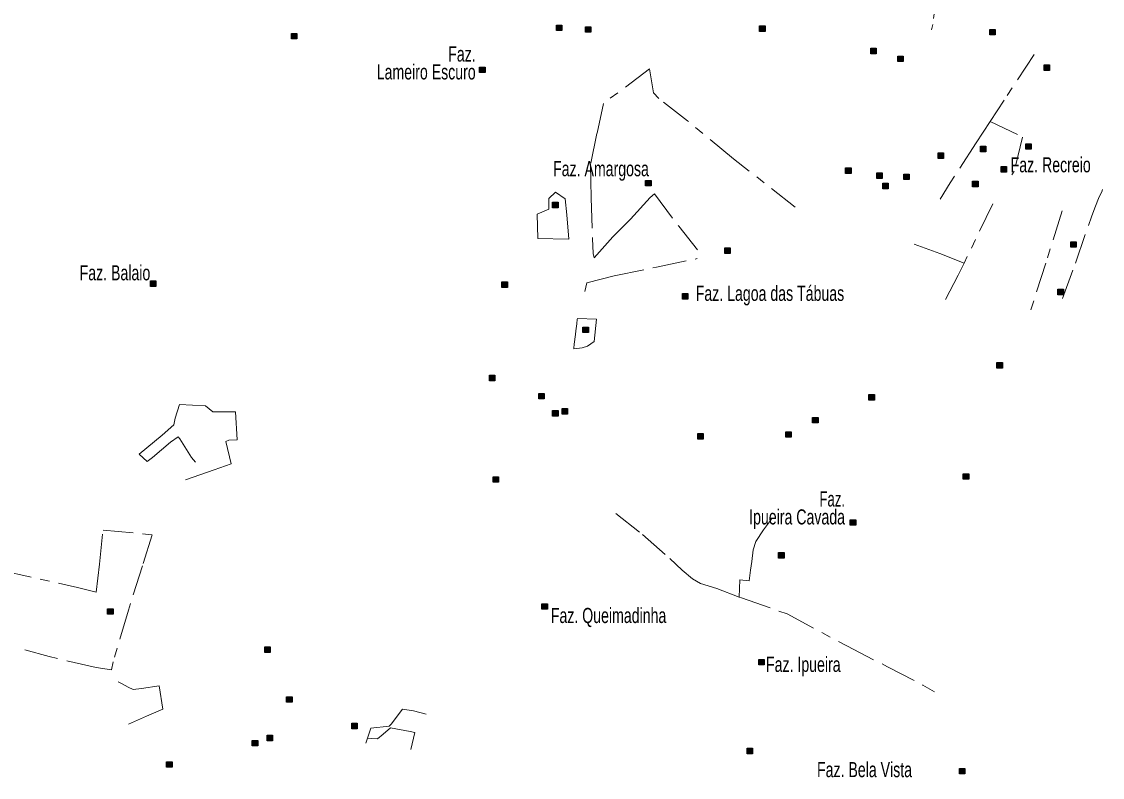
# Model space of a CAD drawing. Extents: x 445.4 to 500, y 8728.7 to 8784.
# Drawn here: x 488.54 to 500, y 8738.13 to 8746.14 of the extents above; entities that cross this region are included whole.
import ezdxf
from ezdxf.enums import TextEntityAlignment as Align

# ---------------------------------------------------------------- set-up
doc = ezdxf.new("R2010")
doc.units = 0
doc.header["$LTSCALE"] = 0.064
doc.linetypes.add('DOT_DASHED', pattern=[7.7, 5, -1.2, 0.3, -1.2])
doc.layers.add('2', color=7, linetype='Continuous', lineweight=25)
doc.layers.add('22', color=7, linetype='DOT_DASHED', lineweight=13)
doc.layers.add('61', color=7, linetype='Continuous')

msp = doc.modelspace()

# ---------------------------------------------------------------- hatches: boundary and pattern name
at = {"layer": '2'}
for points in [[(494.2125, 8746.1016), (494.2705, 8746.1016), (494.2705, 8746.0436), (494.2125, 8746.0436)], [(494.5213, 8746.0849), (494.5793, 8746.0849), (494.5793, 8746.0269), (494.5213, 8746.0269)], [(496.3667, 8746.0936), (496.4247, 8746.0936), (496.4247, 8746.0356), (496.3667, 8746.0356)], [(498.8058, 8746.056), (498.8638, 8746.056), (498.8638, 8745.998), (498.8058, 8745.998)], [(491.4052, 8746.0138), (491.4632, 8746.0138), (491.4632, 8745.9558), (491.4052, 8745.9558)], [(497.5448, 8745.8569), (497.6028, 8745.8569), (497.6028, 8745.7989), (497.5448, 8745.7989)], [(497.8307, 8745.773), (497.8887, 8745.773), (497.8887, 8745.715), (497.8307, 8745.715)], [(493.3992, 8745.6577), (493.4572, 8745.6577), (493.4572, 8745.5997), (493.3992, 8745.5997)], [(499.3821, 8745.68), (499.4401, 8745.68), (499.4401, 8745.622), (499.3821, 8745.622)], [(498.7073, 8744.8186), (498.7653, 8744.8186), (498.7653, 8744.7606), (498.7073, 8744.7606)], [(499.1888, 8744.8442), (499.2468, 8744.8442), (499.2468, 8744.7862), (499.1888, 8744.7862)], [(498.2595, 8744.7472), (498.3175, 8744.7472), (498.3175, 8744.6892), (498.2595, 8744.6892)], [(497.2786, 8744.5894), (497.3366, 8744.5894), (497.3366, 8744.5314), (497.2786, 8744.5314)], [(498.9262, 8744.6032), (498.9842, 8744.6032), (498.9842, 8744.5452), (498.9262, 8744.5452)], [(495.159, 8744.4563), (495.217, 8744.4563), (495.217, 8744.3983), (495.159, 8744.3983)], [(497.6088, 8744.5352), (497.6668, 8744.5352), (497.6668, 8744.4772), (497.6088, 8744.4772)], [(497.8954, 8744.5236), (497.9534, 8744.5236), (497.9534, 8744.4656), (497.8954, 8744.4656)], [(498.6249, 8744.4474), (498.6829, 8744.4474), (498.6829, 8744.3894), (498.6249, 8744.3894)], [(497.6729, 8744.4267), (497.7309, 8744.4267), (497.7309, 8744.3687), (497.6729, 8744.3687)], [(494.1731, 8744.2246), (494.2311, 8744.2246), (494.2311, 8744.1666), (494.1731, 8744.1666)], [(499.6653, 8743.8066), (499.7233, 8743.8066), (499.7233, 8743.7486), (499.6653, 8743.7486)], [(495.997, 8743.7412), (496.055, 8743.7412), (496.055, 8743.6832), (495.997, 8743.6832)], [(489.9093, 8743.3911), (489.9673, 8743.3911), (489.9673, 8743.3331), (489.9093, 8743.3331)], [(493.6358, 8743.3813), (493.6938, 8743.3813), (493.6938, 8743.3233), (493.6358, 8743.3233)], [(499.5285, 8743.3035), (499.5865, 8743.3035), (499.5865, 8743.2455), (499.5285, 8743.2455)], [(495.5484, 8743.2579), (495.6064, 8743.2579), (495.6064, 8743.1999), (495.5484, 8743.1999)], [(494.4935, 8742.9028), (494.5515, 8742.9028), (494.5515, 8742.8448), (494.4935, 8742.8448)], [(498.8824, 8742.5264), (498.9404, 8742.5264), (498.9404, 8742.4684), (498.8824, 8742.4684)], [(493.5027, 8742.392), (493.5607, 8742.392), (493.5607, 8742.334), (493.5027, 8742.334)], [(494.0252, 8742.1997), (494.0832, 8742.1997), (494.0832, 8742.1417), (494.0252, 8742.1417)], [(497.525, 8742.1877), (497.583, 8742.1877), (497.583, 8742.1297), (497.525, 8742.1297)], [(494.2734, 8742.0382), (494.3314, 8742.0382), (494.3314, 8741.9802), (494.2734, 8741.9802)], [(494.1731, 8742.0172), (494.2311, 8742.0172), (494.2311, 8741.9592), (494.1731, 8741.9592)], [(496.9286, 8741.946), (496.9866, 8741.946), (496.9866, 8741.888), (496.9286, 8741.888)], [(495.7111, 8741.7734), (495.7691, 8741.7734), (495.7691, 8741.7154), (495.7111, 8741.7154)], [(496.6434, 8741.7926), (496.7014, 8741.7926), (496.7014, 8741.7346), (496.6434, 8741.7346)], [(493.5422, 8741.3169), (493.6002, 8741.3169), (493.6002, 8741.2589), (493.5422, 8741.2589)], [(498.5249, 8741.3474), (498.5829, 8741.3474), (498.5829, 8741.2894), (498.5249, 8741.2894)], [(497.3279, 8740.8611), (497.3859, 8740.8611), (497.3859, 8740.8031), (497.3279, 8740.8031)], [(496.5684, 8740.5135), (496.6264, 8740.5135), (496.6264, 8740.4555), (496.5684, 8740.4555)], [(489.4558, 8739.9184), (489.5138, 8739.9184), (489.5138, 8739.8604), (489.4558, 8739.8604)], [(494.0597, 8739.9705), (494.1177, 8739.9705), (494.1177, 8739.9125), (494.0597, 8739.9125)], [(491.1219, 8739.5139), (491.1799, 8739.5139), (491.1799, 8739.4559), (491.1219, 8739.4559)], [(496.3568, 8739.3815), (496.4148, 8739.3815), (496.4148, 8739.3235), (496.3568, 8739.3235)], [(491.3536, 8738.9862), (491.4116, 8738.9862), (491.4116, 8738.9282), (491.3536, 8738.9282)], [(492.0437, 8738.7051), (492.1017, 8738.7051), (492.1017, 8738.6471), (492.0437, 8738.6471)], [(490.9888, 8738.5226), (491.0468, 8738.5226), (491.0468, 8738.4646), (490.9888, 8738.4646)], [(491.1465, 8738.5769), (491.2045, 8738.5769), (491.2045, 8738.5189), (491.1465, 8738.5189)], [(496.2336, 8738.4396), (496.2916, 8738.4396), (496.2916, 8738.3816), (496.2336, 8738.3816)], [(490.0818, 8738.2958), (490.1398, 8738.2958), (490.1398, 8738.2378), (490.0818, 8738.2378)], [(498.4848, 8738.226), (498.5428, 8738.226), (498.5428, 8738.168), (498.4848, 8738.168)]]:
    msp.add_hatch(color=256, dxfattribs=at).paths.add_polyline_path(points)

# ---------------------------------------------------------------- linework, layer by layer
for points in [[(494.2125, 8746.1016), (494.2705, 8746.1016), (494.2705, 8746.0436), (494.2125, 8746.0436)], [(494.5213, 8746.0849), (494.5793, 8746.0849), (494.5793, 8746.0269), (494.5213, 8746.0269)], [(496.3667, 8746.0936), (496.4247, 8746.0936), (496.4247, 8746.0356), (496.3667, 8746.0356)], [(498.8058, 8746.056), (498.8638, 8746.056), (498.8638, 8745.998), (498.8058, 8745.998)], [(491.4052, 8746.0138), (491.4632, 8746.0138), (491.4632, 8745.9558), (491.4052, 8745.9558)], [(497.5448, 8745.8569), (497.6028, 8745.8569), (497.6028, 8745.7989), (497.5448, 8745.7989)], [(497.8307, 8745.773), (497.8887, 8745.773), (497.8887, 8745.715), (497.8307, 8745.715)], [(493.3992, 8745.6577), (493.4572, 8745.6577), (493.4572, 8745.5997), (493.3992, 8745.5997)], [(499.3821, 8745.68), (499.4401, 8745.68), (499.4401, 8745.622), (499.3821, 8745.622)], [(498.7073, 8744.8186), (498.7653, 8744.8186), (498.7653, 8744.7606), (498.7073, 8744.7606)], [(499.1888, 8744.8442), (499.2468, 8744.8442), (499.2468, 8744.7862), (499.1888, 8744.7862)], [(498.2595, 8744.7472), (498.3175, 8744.7472), (498.3175, 8744.6892), (498.2595, 8744.6892)], [(497.2786, 8744.5894), (497.3366, 8744.5894), (497.3366, 8744.5314), (497.2786, 8744.5314)], [(498.9262, 8744.6032), (498.9842, 8744.6032), (498.9842, 8744.5452), (498.9262, 8744.5452)], [(495.159, 8744.4563), (495.217, 8744.4563), (495.217, 8744.3983), (495.159, 8744.3983)], [(497.6088, 8744.5352), (497.6668, 8744.5352), (497.6668, 8744.4772), (497.6088, 8744.4772)], [(497.8954, 8744.5236), (497.9534, 8744.5236), (497.9534, 8744.4656), (497.8954, 8744.4656)], [(498.6249, 8744.4474), (498.6829, 8744.4474), (498.6829, 8744.3894), (498.6249, 8744.3894)], [(497.6729, 8744.4267), (497.7309, 8744.4267), (497.7309, 8744.3687), (497.6729, 8744.3687)], [(494.1731, 8744.2246), (494.2311, 8744.2246), (494.2311, 8744.1666), (494.1731, 8744.1666)], [(499.6653, 8743.8066), (499.7233, 8743.8066), (499.7233, 8743.7486), (499.6653, 8743.7486)], [(495.997, 8743.7412), (496.055, 8743.7412), (496.055, 8743.6832), (495.997, 8743.6832)], [(489.9093, 8743.3911), (489.9673, 8743.3911), (489.9673, 8743.3331), (489.9093, 8743.3331)], [(493.6358, 8743.3813), (493.6938, 8743.3813), (493.6938, 8743.3233), (493.6358, 8743.3233)], [(499.5285, 8743.3035), (499.5865, 8743.3035), (499.5865, 8743.2455), (499.5285, 8743.2455)], [(495.5484, 8743.2579), (495.6064, 8743.2579), (495.6064, 8743.1999), (495.5484, 8743.1999)], [(494.4935, 8742.9028), (494.5515, 8742.9028), (494.5515, 8742.8448), (494.4935, 8742.8448)], [(498.8824, 8742.5264), (498.9404, 8742.5264), (498.9404, 8742.4684), (498.8824, 8742.4684)], [(493.5027, 8742.392), (493.5607, 8742.392), (493.5607, 8742.334), (493.5027, 8742.334)], [(494.0252, 8742.1997), (494.0832, 8742.1997), (494.0832, 8742.1417), (494.0252, 8742.1417)], [(497.525, 8742.1877), (497.583, 8742.1877), (497.583, 8742.1297), (497.525, 8742.1297)], [(494.2734, 8742.0382), (494.3314, 8742.0382), (494.3314, 8741.9802), (494.2734, 8741.9802)], [(494.1731, 8742.0172), (494.2311, 8742.0172), (494.2311, 8741.9592), (494.1731, 8741.9592)], [(496.9286, 8741.946), (496.9866, 8741.946), (496.9866, 8741.888), (496.9286, 8741.888)], [(495.7111, 8741.7734), (495.7691, 8741.7734), (495.7691, 8741.7154), (495.7111, 8741.7154)], [(496.6434, 8741.7926), (496.7014, 8741.7926), (496.7014, 8741.7346), (496.6434, 8741.7346)], [(493.5422, 8741.3169), (493.6002, 8741.3169), (493.6002, 8741.2589), (493.5422, 8741.2589)], [(498.5249, 8741.3474), (498.5829, 8741.3474), (498.5829, 8741.2894), (498.5249, 8741.2894)], [(497.3279, 8740.8611), (497.3859, 8740.8611), (497.3859, 8740.8031), (497.3279, 8740.8031)], [(496.5684, 8740.5135), (496.6264, 8740.5135), (496.6264, 8740.4555), (496.5684, 8740.4555)], [(489.4558, 8739.9184), (489.5138, 8739.9184), (489.5138, 8739.8604), (489.4558, 8739.8604)], [(494.0597, 8739.9705), (494.1177, 8739.9705), (494.1177, 8739.9125), (494.0597, 8739.9125)], [(491.1219, 8739.5139), (491.1799, 8739.5139), (491.1799, 8739.4559), (491.1219, 8739.4559)], [(496.3568, 8739.3815), (496.4148, 8739.3815), (496.4148, 8739.3235), (496.3568, 8739.3235)], [(491.3536, 8738.9862), (491.4116, 8738.9862), (491.4116, 8738.9282), (491.3536, 8738.9282)], [(492.0437, 8738.7051), (492.1017, 8738.7051), (492.1017, 8738.6471), (492.0437, 8738.6471)], [(490.9888, 8738.5226), (491.0468, 8738.5226), (491.0468, 8738.4646), (490.9888, 8738.4646)], [(491.1465, 8738.5769), (491.2045, 8738.5769), (491.2045, 8738.5189), (491.1465, 8738.5189)], [(496.2336, 8738.4396), (496.2916, 8738.4396), (496.2916, 8738.3816), (496.2336, 8738.3816)], [(490.0818, 8738.2958), (490.1398, 8738.2958), (490.1398, 8738.2378), (490.0818, 8738.2378)], [(498.4848, 8738.226), (498.5428, 8738.226), (498.5428, 8738.168), (498.4848, 8738.168)]]:
    msp.add_lwpolyline(points, close=True, dxfattribs=at)
at = {"layer": '22'}
for p, q in [((498.8377, 8744.208), (498.5335, 8743.5794)), ((492.1941, 8738.494), (492.2101, 8738.5453))]:
    msp.add_line(p, q, dxfattribs=at)
for points in [[(498.6405, 8746.6201), (498.6241, 8746.4367), (498.2551, 8746.4894), (498.2024, 8746.1078), (498.1904, 8746.0518)], [(499.2757, 8745.7897), (498.9593, 8745.3076), (498.8116, 8745.0802)], [(496.7451, 8744.1724), (496.0891, 8744.6862), (495.6017, 8745.0893), (495.2971, 8745.3251), (495.2437, 8745.3859), (495.1999, 8745.6378), (494.7106, 8745.2718), (494.6421, 8744.9524), (494.5753, 8744.6271), (494.5789, 8744.4474), (494.58, 8744.2713), (494.5964, 8743.8419), (494.604, 8743.6822), (494.6116, 8743.6366), (494.8097, 8743.8571), (495, 8744.0473), (495.2057, 8744.2755), (495.2514, 8744.3135), (495.5103, 8743.9712), (495.7629, 8743.6516)], [(498.8116, 8745.0802), (498.6615, 8744.8542), (498.3881, 8744.43), (498.2802, 8744.2565)], [(498.8116, 8745.0802), (499.1542, 8744.9166), (499.0653, 8744.5556), (499.0418, 8744.5149)], [(499.8844, 8744.0722), (499.921, 8744.1648), (499.9672, 8744.2821), (499.9928, 8744.3358), (500, 8744.359)], [(499.5748, 8744.1335), (499.3998, 8743.5814), (499.2175, 8743.0064)], [(499.5758, 8743.2061), (499.7136, 8743.5814), (499.8844, 8744.0722)], [(498.006, 8743.7809), (498.2775, 8743.6811), (498.5335, 8743.5794)], [(494.5145, 8743.2799), (494.5355, 8743.3704), (494.8249, 8743.4464), (495.2742, 8743.5377), (495.7034, 8743.6275)], [(498.5335, 8743.5794), (498.4724, 8743.4532), (498.3364, 8743.1958)], [(494.4348, 8742.9934), (494.6385, 8742.9871), (494.6115, 8742.7508), (494.5425, 8742.7008), (494.4871, 8742.6833), (494.3965, 8742.6738), (494.3972, 8742.6784)], [(494.4201, 8742.8612), (494.4303, 8742.9371), (494.4334, 8742.9857), (494.4348, 8742.9934)], [(494.3972, 8742.6784), (494.402, 8742.7218), (494.4145, 8742.8238), (494.4201, 8742.8612)], [(490.2828, 8741.2841), (490.5862, 8741.3888), (490.7658, 8741.4535), (490.7098, 8741.6916), (490.7393, 8741.7034), (490.8305, 8741.7092), (490.8099, 8742.0061), (490.5715, 8742.0032), (490.4921, 8742.0678), (490.2165, 8742.0811), (490.1721, 8741.939), (490.1588, 8741.868), (490.0343, 8741.757), (489.7898, 8741.5573), (489.8743, 8741.4774), (489.9321, 8741.5218), (490.1232, 8741.6816), (490.2032, 8741.7393), (490.221, 8741.7171), (490.3454, 8741.5218), (490.3873, 8741.4702)], [(494.8424, 8740.9263), (495.1266, 8740.7042), (495.4141, 8740.4509), (495.5452, 8740.3284), (495.6551, 8740.2355), (495.7397, 8740.1848), (495.913, 8740.1342), (496.1513, 8740.042)], [(496.1513, 8740.042), (496.1585, 8740.2253), (496.2548, 8740.2138), (496.2702, 8740.3254), (496.2856, 8740.4177), (496.2972, 8740.5409), (496.328, 8740.6294), (496.4089, 8740.7525), (496.4913, 8740.867)], [(488.4295, 8739.5276), (488.2535, 8739.5475), (488.2876, 8739.7372), (488.3022, 8739.9852), (488.3316, 8740.3229), (489.1352, 8740.143), (489.3349, 8740.0943), (489.3689, 8740.391), (489.4079, 8740.7509), (489.929, 8740.7023), (489.8267, 8740.3716), (489.6758, 8739.9046), (489.5151, 8739.355), (489.4954, 8739.2703), (489.3347, 8739.2946), (488.8379, 8739.4113), (488.5798, 8739.4817)], [(496.1513, 8740.042), (496.1752, 8740.0328), (496.6572, 8739.8639), (497.2901, 8739.5233), (497.7214, 8739.3038), (498.0977, 8739.1095), (498.2221, 8739.0392)], [(489.6766, 8738.6968), (489.8675, 8738.7788), (490.0411, 8738.8527), (490.0013, 8739.1027), (489.8135, 8739.0715), (489.7253, 8739.063), (489.6741, 8739.0857), (489.6086, 8739.1226), (489.5694, 8739.1428)], [(492.4659, 8738.698), (492.4628, 8738.695), (492.5823, 8738.8531), (492.6998, 8738.8347), (492.8312, 8738.8022)], [(492.2101, 8738.5453), (492.2448, 8738.6535), (492.4405, 8738.6727), (492.4628, 8738.695), (492.4659, 8738.698)], [(492.4542, 8738.6558), (492.3749, 8738.5907), (492.317, 8738.5389), (492.2515, 8738.5419), (492.2101, 8738.5453)], [(492.67, 8738.4258), (492.7113, 8738.6059), (492.6627, 8738.6181), (492.4542, 8738.6558)]]:
    msp.add_lwpolyline(points, dxfattribs=at)
msp.add_lwpolyline([(494.1328, 8744.1536), (494.01, 8744.1005), (494.0176, 8743.8419), (494.3451, 8743.8343), (494.3222, 8744.0929), (494.307, 8744.2602), (494.2031, 8744.3319), (494.1328, 8744.2667)], close=True, dxfattribs=at)

# ---------------------------------------------------------------- texts
at = {"layer": '61'}
for s, width, p in [('                  Faz.', 0.7, (493.3572, 8745.7164)), ('Lameiro Escuro', 0.7, (493.3572, 8745.5264)), ('Faz. Balaio', 0.7, (489.9084, 8743.398)), ('Faz.', 0.65, (497.2718, 8741.0012)), ('Ipueira Cavada', 0.7, (497.2718, 8740.8112))]:
    msp.add_text(s, height=0.16, dxfattribs=dict(at, width=width)).set_placement(p, align=Align.RIGHT)
at = {"layer": '61', "width": 0.7}
for s, p in [('Faz. Recreio', (499.0275, 8744.5424)), ('Faz. Amargosa', (494.1778, 8744.5009)), ('Faz. Lagoa das Tábuas', (495.6899, 8743.1801)), ('Faz. Queimadinha', (494.1537, 8739.7667)), ('Faz. Ipueira', (496.4345, 8739.2488)), ('Faz. Bela Vista', (496.9752, 8738.1335))]:
    msp.add_text(s, height=0.16, dxfattribs=at).set_placement(p)

doc.saveas('drawing.dxf')
